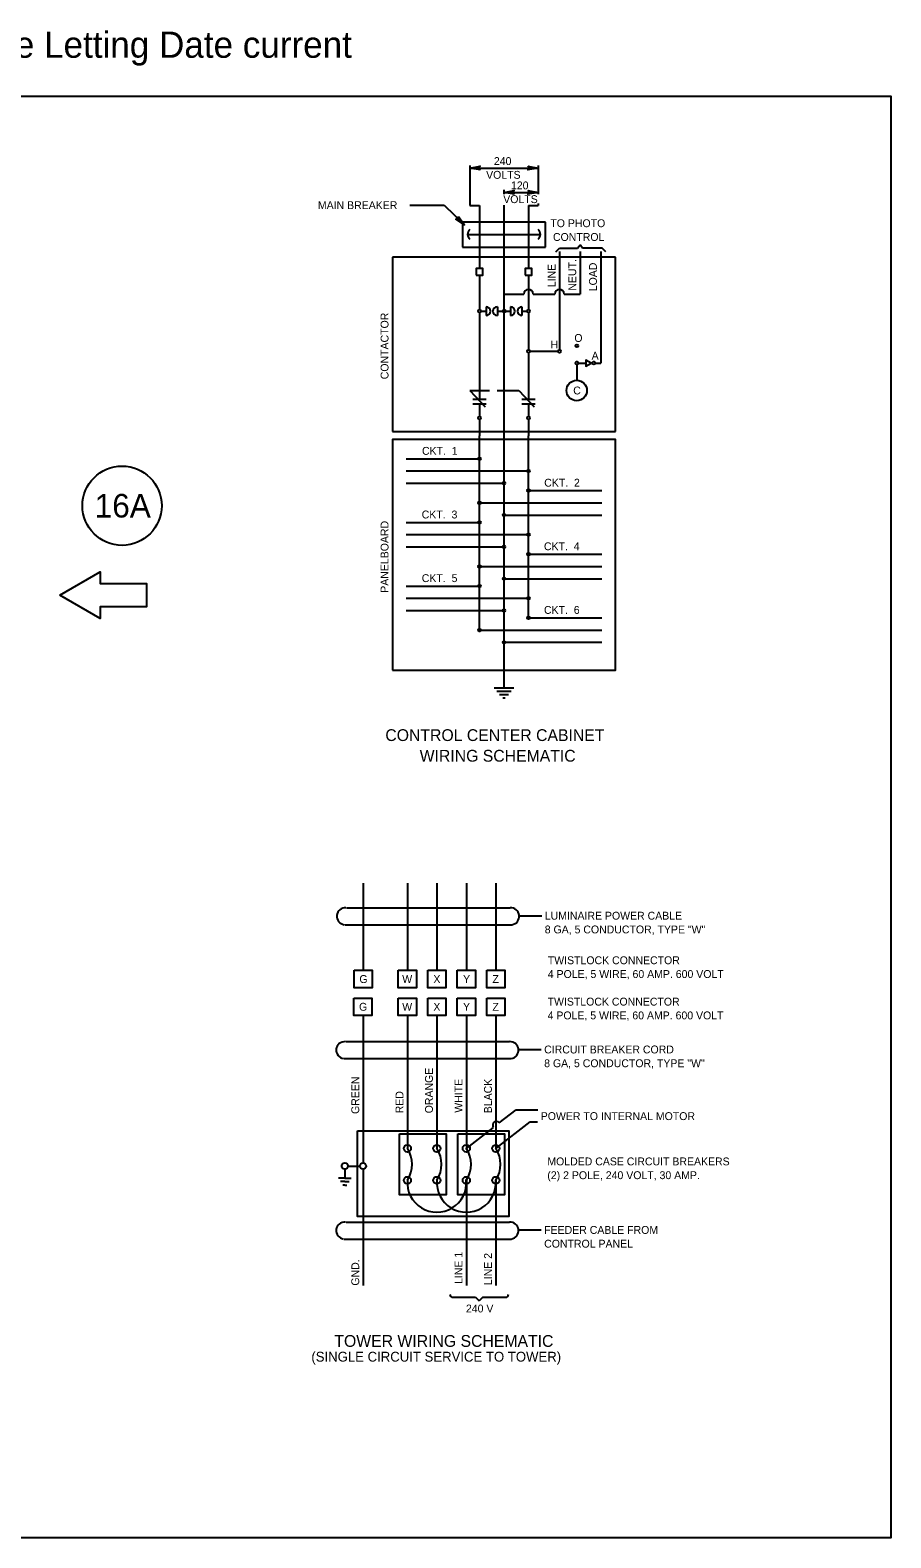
# Model space of a CAD drawing. Extents: x 99968 to 128667, y 90163 to 102182.
# Drawn here: x 117154 to 118467, y 93472 to 95772 of the extents above; entities that cross this region are included whole.
import ezdxf

# ---------------------------------------------------------------- set-up
doc = ezdxf.new("R2010")
doc.units = 0
for name, color, linetype in [('Border Prelim Stamp', 7, 'Continuous'), ('Default', 7, 'Continuous'), ('Level 7', 7, 'Continuous'), ('RD Standard Plans Active', 7, 'Continuous')]:
    doc.layers.add(name, color=color, linetype=linetype)

msp = doc.modelspace()

# ---------------------------------------------------------------- linework, layer by layer
at = {"layer": 'Border Prelim Stamp'}
msp.add_lwpolyline([(117198.9, 94910), (117260.4, 94945.5), (117260.4, 94927.7), (117331.3, 94927.7), (117331.3, 94892.3), (117260.4, 94892.3), (117260.4, 94874.5)], close=True, dxfattribs=at)
msp.add_ellipse((117294.1, 95046.6), major_axis=(-60.5, 0), ratio=0.999984, dxfattribs=at)
at = {"layer": 'Default'}
msp.add_lwpolyline([(115267.5, 95671.5), (118467.2, 95671.5), (118467.2, 93471.9), (115267.5, 93471.9)], close=True, dxfattribs=at)
at = {"layer": 'RD Standard Plans Active'}
for p, q in [((117824.6, 95565.5), (117824.6, 95504.5)), ((117824.6, 95561.8), (117929.1, 95561.8)), ((117929.1, 95565.5), (117929.1, 95521.7)), ((117876.9, 95522.1), (117876.9, 95528.3)), ((117876.9, 95524.7), (117929.1, 95524.7)), ((117929.1, 95507.7), (117929.1, 95504.5)), ((117733.4, 95505.1), (117785.6, 95505.1)), ((117785.6, 95505.1), (117816.8, 95475.1)), ((117824.6, 95504.5), (117839.5, 95504.5)), ((117839.5, 95504.5), (117839.5, 95432.1)), ((117876.9, 94768.5), (117876.9, 95505.3)), ((117914.2, 95504.5), (117929.1, 95504.5)), ((117914.2, 95504.5), (117914.2, 95432.1)), ((117940.4, 95479.1), (117813.3, 95479.1)), ((117813.3, 95479.1), (117813.3, 95441.1)), ((117821.3, 95460.6), (117932.4, 95460.6)), ((117940.4, 95441.1), (117940.4, 95479.1)), ((117813.3, 95441.1), (117940.4, 95441.1)), ((117956.1, 95433.8), (117961.8, 95439.5)), ((117961.8, 95439.5), (117988.8, 95439.5)), ((117988.8, 95439.5), (117992.9, 95444.6)), ((117996.9, 95439.5), (117992.9, 95444.6)), ((118026.7, 95439.5), (117996.9, 95439.5)), ((118032.4, 95433.8), (118026.7, 95439.5)), ((118046.8, 95425.9), (117706.6, 95425.9)), ((117706.6, 95425.9), (117706.6, 95159.7)), ((117839.5, 95432.1), (117839.5, 95408.7)), ((117914.2, 95432.1), (117914.2, 95408.7)), ((117961.5, 95434.4), (117961.5, 95284.4)), ((117993.1, 95434.4), (117993.1, 95369.5)), ((118024.6, 95434.4), (118024.6, 95264.3)), ((118046.8, 95159.7), (118046.8, 95425.9)), ((117839.5, 95398.1), (117839.5, 95345.7)), ((117914.2, 95398.2), (117914.2, 95345.7)), ((117876.8, 95369.5), (117907, 95369.5)), ((117921.4, 95369.5), (117954.3, 95369.5)), ((117968.7, 95369.5), (117993.1, 95369.5)), ((117849.6, 95350.1), (117849.6, 95336.8)), ((117866.8, 95350.1), (117866.8, 95336.8)), ((117887, 95350.1), (117887, 95336.8)), ((117904.1, 95350.1), (117904.1, 95336.8)), ((117839.5, 95341.3), (117839.5, 95209.2)), ((117841.7, 95343.5), (117849.6, 95343.5)), ((117866.8, 95343.5), (117874.6, 95343.5)), ((117879.1, 95343.5), (117887, 95343.5)), ((117904.1, 95343.5), (117912, 95343.5)), ((117914.2, 95341.3), (117914.2, 95284.4)), ((117914.2, 95280), (117914.2, 95209.2)), ((117916.4, 95282.2), (117959.3, 95282.2)), ((117987.8, 95262.1), (117987.8, 95238)), ((117990, 95264.3), (118001.9, 95264.3)), ((118016.3, 95264.3), (118024.6, 95264.3)), ((117824.6, 95222.6), (117848.2, 95197.4)), ((117824.6, 95222.6), (117854.9, 95222.6)), ((117829.2, 95209.2), (117849.8, 95209.2)), ((117866.6, 95222.6), (117899.3, 95222.6)), ((117899.3, 95222.6), (117922.9, 95197.4)), ((117903.9, 95209.2), (117924.5, 95209.2)), ((117829.2, 95201.8), (117849.8, 95201.8)), ((117839.5, 95201.8), (117839.5, 95182.7)), ((117903.9, 95201.8), (117924.5, 95201.8)), ((117914.2, 95201.8), (117914.2, 95182.7)), ((117839.5, 95178.3), (117839.5, 95153.1)), ((117914.2, 95178.3), (117914.2, 95153.1)), ((117706.6, 95159.7), (118046.8, 95159.7)), ((117839.5, 94856.9), (117839.5, 95153.1)), ((117914.2, 94875.6), (117914.2, 95153.1)), ((117727.5, 95118.3), (117839.5, 95118.3)), ((117727.5, 95099.6), (117914.2, 95099.6)), ((117727.5, 95080.9), (117876.9, 95080.9)), ((117914.2, 95069.7), (118026.2, 95069.7)), ((117839.5, 95051.1), (118026.2, 95051.1)), ((117876.9, 95032.4), (118026.2, 95032.4)), ((117727.5, 95021.2), (117839.5, 95021.2)), ((117727.5, 95002.5), (117914.2, 95002.5)), ((117727.5, 94983.9), (117876.9, 94983.9)), ((117839.5, 94954), (118026.2, 94954)), ((117914.2, 94972.7), (118026.2, 94972.7)), ((117876.9, 94935.3), (118026.2, 94935.3)), ((117727.5, 94924.1), (117839.5, 94924.1)), ((117727.5, 94905.4), (117914.2, 94905.4)), ((117727.5, 94886.8), (117876.9, 94886.8)), ((117914.2, 94875.6), (118026.2, 94875.6)), ((117839.5, 94856.9), (118026.2, 94856.9)), ((117876.9, 94838.2), (118026.2, 94838.2)), ((117861.9, 94768.5), (117891.8, 94768.5)), ((117865.9, 94763.5), (117887.8, 94763.5)), ((117869.9, 94758.6), (117883.8, 94758.6)), ((117874.9, 94753.6), (117878.8, 94753.6)), ((117661.9, 94470.7), (117661.9, 94337.8)), ((117729.4, 94470.7), (117729.4, 94337.8)), ((117774.4, 94470.7), (117774.4, 94337.8)), ((117819.4, 94470.7), (117819.4, 94337.8)), ((117864.4, 94470.7), (117864.4, 94337.8)), ((117636.7, 94433.2), (117886.1, 94433.2)), ((117633.9, 94407.3), (117889, 94407.3)), ((117900.1, 94421.1), (117934.6, 94421.1)), ((117661.9, 94268.7), (117661.9, 94043.9)), ((117729.4, 94268.7), (117729.4, 94066.1)), ((117774.4, 94268.7), (117774.4, 94066.1)), ((117819.4, 94268.7), (117819.4, 94066.1)), ((117864.4, 94268.7), (117864.4, 94066.1)), ((117635.8, 94229), (117885.2, 94229)), ((117632.9, 94203.1), (117888, 94203.1)), ((117899.1, 94217), (117933.7, 94217)), ((117864.4, 94066.1), (117916.7, 94106.5)), ((117869.6, 94105), (117895.5, 94125)), ((117895.5, 94125), (117928.5, 94125)), ((117916.7, 94106.5), (117928.2, 94106.5)), ((117819.4, 94066.1), (117860.8, 94098.2)), ((117634, 94034.2), (117634, 94020.7)), ((117638.7, 94039.2), (117656.9, 94039.2)), ((117634, 94020.7), (117624.2, 94020.7)), ((117634, 94015.6), (117627.3, 94015.6)), ((117634, 94020.7), (117643.8, 94020.7)), ((117634, 94015.6), (117640.6, 94015.6)), ((117661.9, 94033.6), (117661.9, 93857.1)), ((117819.4, 94017.4), (117819.4, 93857.1)), ((117864.4, 94017.4), (117864.4, 93857.1)), ((117633.9, 94010.2), (117631.1, 94010.2)), ((117634, 94010.2), (117636.8, 94010.2)), ((117635.8, 93953.7), (117885.2, 93953.7)), ((117899.1, 93941.7), (117933.7, 93941.7)), ((117632.9, 93927.8), (117888, 93927.8)), ((117798.6, 93839), (117833.3, 93839)), ((117833.3, 93839), (117839, 93833.3)), ((117844.6, 93839), (117839, 93833.3)), ((117844.6, 93839), (117879.4, 93839))]:
    msp.add_line(p, q, dxfattribs=at)
for points in [[(117840.3, 95559.2), (117824.6, 95561.8), (117840.3, 95564.5), (117837.8, 95561.8)], [(117913.4, 95564.5), (117929.1, 95561.8), (117913.4, 95559.2), (117915.9, 95561.8)], [(117892.5, 95522), (117876.9, 95524.7), (117892.5, 95527.4), (117890.1, 95524.7)], [(117913.4, 95527.4), (117929.1, 95524.7), (117913.4, 95522), (117915.9, 95524.7)], [(117807.3, 95487.9), (117816.8, 95475.1), (117803.6, 95484), (117807.3, 95484.2)], [(117834.3, 95398.2), (117844.8, 95398.2), (117844.8, 95408.7), (117834.3, 95408.7)], [(117909, 95398.2), (117919.5, 95398.2), (117919.5, 95408.7), (117909, 95408.7)], [(118009.8, 95264.3), (118001.9, 95268.8), (118001.9, 95259.7)], [(117706.6, 94795.5), (118046.8, 94795.5), (118046.8, 95147.5), (117706.6, 95147.5)], [(117648.1, 94337.8), (117675.7, 94337.8), (117675.7, 94311.1), (117648.1, 94311.1)], [(117715.6, 94337.8), (117743.2, 94337.8), (117743.2, 94311.1), (117715.6, 94311.1)], [(117760.6, 94337.8), (117788.2, 94337.8), (117788.2, 94311.1), (117760.6, 94311.1)], [(117805.6, 94337.8), (117833.2, 94337.8), (117833.2, 94311.1), (117805.6, 94311.1)], [(117850.6, 94337.8), (117878.2, 94337.8), (117878.2, 94311.1), (117850.6, 94311.1)], [(117647.6, 94295.4), (117675.2, 94295.4), (117675.2, 94268.7), (117647.6, 94268.7)], [(117715.6, 94295.4), (117743.2, 94295.4), (117743.2, 94268.7), (117715.6, 94268.7)], [(117760.6, 94295.4), (117788.2, 94295.4), (117788.2, 94268.7), (117760.6, 94268.7)], [(117805.6, 94295.4), (117833.2, 94295.4), (117833.2, 94268.7), (117805.6, 94268.7)], [(117850.6, 94295.4), (117878.2, 94295.4), (117878.2, 94268.7), (117850.6, 94268.7)], [(117653.4, 94093), (117884.4, 94093), (117884.4, 93962), (117653.4, 93962)], [(117717.4, 94088.2), (117788.6, 94088.2), (117788.6, 93995.3), (117717.4, 93995.3)], [(117806.6, 94088.2), (117877.8, 94088.2), (117877.8, 93995.3), (117806.6, 93995.3)]]:
    msp.add_lwpolyline(points, close=True, dxfattribs=at)
for centre, radius in [((117839.5, 95343.5), 2.21), ((117876.9, 95343.5), 2.21), ((117914.2, 95343.5), 2.21), ((117914.2, 95282.2), 2.21), ((117961.5, 95282.2), 2.21), ((117987.8, 95290.6), 2.21), ((117987.8, 95264.3), 2.21), ((118014.1, 95264.3), 2.21), ((117987.8, 95222.4), 15.6), ((117839.5, 95180.5), 2.21), ((117914.2, 95180.5), 2.21), ((117839.5, 95118.3), 1.99), ((117914.2, 95099.6), 1.99), ((117876.9, 95080.9), 1.99), ((117914.2, 95069.7), 1.99), ((117839.5, 95051.1), 1.99), ((117839.5, 95021.2), 1.99), ((117876.9, 95032.4), 1.99), ((117914.2, 95002.5), 1.99), ((117876.9, 94983.9), 1.99), ((117839.5, 94954), 1.99), ((117914.2, 94972.7), 1.99), ((117876.9, 94935.3), 1.99), ((117839.5, 94924.1), 1.99), ((117876.9, 94886.8), 1.99), ((117914.2, 94905.4), 1.99), ((117914.2, 94875.6), 1.99), ((117839.5, 94856.9), 1.99), ((117876.9, 94838.2), 1.99), ((117876.9, 94838.2), 1.99), ((117729.4, 94066.1), 5.54), ((117774.4, 94066.1), 5.54), ((117819.4, 94066.1), 5.54), ((117864.4, 94066.1), 5.54), ((117634, 94039.2), 4.73), ((117661.6, 94039.2), 4.73), ((117729.4, 94017.4), 5.54), ((117774.4, 94017.4), 5.54), ((117819.4, 94017.4), 5.54), ((117864.4, 94017.4), 5.54)]:
    msp.add_circle(centre, radius, dxfattribs=at)
for centre, radius, start, end in [((117830.3, 95460.6), 8.96, 126.8699, 233.1301), ((117923.5, 95460.6), 8.96, 306.8699, 53.1301), ((117914.2, 95369.5), 7.21, 0, 180), ((117961.5, 95369.5), 7.21, 0, 180), ((117849.6, 95343.5), 6.64, 270, 90), ((117866.7, 95343.5), 6.64, 90, 270), ((117887, 95343.5), 6.64, 270, 90), ((117904.1, 95343.5), 6.64, 90, 270), ((117634.8, 94420.2), 13, 85.7861, 261.6234), ((117887.1, 94420.2), 13, 278.3766, 94.2139), ((117633.9, 94216), 13, 85.7861, 261.6234), ((117886.1, 94216), 13, 278.3766, 94.2139), ((117865.2, 94101.6), 5.54, 38.1296, 217.1791), ((117691.8, 94041.7), 44.9, 327.1836, 33.0606), ((117736.7, 94041.8), 44.9, 327.0615, 32.9385), ((117781.7, 94041.8), 44.9, 327.0615, 32.9385), ((117826.7, 94041.8), 44.9, 327.0615, 32.9385), ((117774.4, 94013.7), 45, 175.318, 4.6724), ((117819.4, 94013.7), 45, 175.318, 4.6724), ((117633.9, 93940.7), 13, 85.7861, 261.6234), ((117886.1, 93940.7), 13, 278.3766, 94.2139), ((117798.7, 93843.4), 4.39, 181.1495, 270.7231), ((117879.4, 93843.4), 4.39, 269.2769, 358.8505)]:
    msp.add_arc(centre, radius, start, end, dxfattribs=at)

# ---------------------------------------------------------------- texts
at = {"layer": 'Border Prelim Stamp'}
msp.add_text('16A', height=36, dxfattribs=at).set_placement((117252.3, 95028.6))
at = {"layer": 'Level 7'}
msp.add_text('Effective Letting Date current', height=40, dxfattribs=at).set_placement((116955, 95730))
at = {"layer": 'RD Standard Plans Active'}
for s, height, p in [('240', 12, (117861.4, 95566.4)), ('VOLTS', 12, (117849.6, 95545.4)), ('120', 12, (117887.5, 95529.3)), ('MAIN BREAKER ', 12, (117592.9, 95499.1)), ('VOLTS', 12, (117875.7, 95508.3)), ('TO PHOTO', 12, (117947.6, 95471.6)), ('CONTROL', 12, (117951.6, 95450.6)), ('O', 12, (117984.2, 95296.5)), ('H', 12, (117948, 95286.5)), ('A', 12, (118010.6, 95269.5)), ('C', 12, (117982.5, 95216.4)), ('CKT.  1', 12, (117751.7, 95124.3)), ('CKT.  2', 12, (117938.2, 95075.7)), ('CKT.  3', 12, (117751.3, 95027.2)), ('CKT.  4', 12, (117937.8, 94978.7)), ('CKT.  5', 12, (117751.4, 94930.1)), ('CKT.  6', 12, (117937.9, 94881.6)), ('CONTROL CENTER CABINET', 18, (117695.8, 94687.6)), ('WIRING SCHEMATIC', 18, (117748.2, 94656.1)), (' LUMINAIRE POWER CABLE', 12, (117934.6, 94415.1)), (' 8 GA, 5 CONDUCTOR, TYPE "W"', 12, (117934.6, 94394.1)), ('TWISTLOCK CONNECTOR', 12, (117943.7, 94347.1)), ('4 POLE, 5 WIRE, 60 AMP. 600 VOLT', 12, (117943.7, 94326.1)), ('G', 12, (117656.2, 94318.4)), ('W', 12, (117721.6, 94318.4)), ('X', 12, (117769.1, 94318.4)), ('Y', 12, (117814.4, 94318.4)), ('Z', 12, (117859.2, 94318.4)), ('G', 12, (117655.7, 94276.1)), ('W', 12, (117721.6, 94276.1)), ('X', 12, (117769.1, 94276.1)), ('Y', 12, (117814.4, 94276.1)), ('Z', 12, (117859.2, 94276.1)), ('TWISTLOCK CONNECTOR', 12, (117943.4, 94284)), ('4 POLE, 5 WIRE, 60 AMP. 600 VOLT', 12, (117943.4, 94263)), (' CIRCUIT BREAKER CORD', 12, (117933.7, 94211)), (' 8 GA, 5 CONDUCTOR, TYPE "W"', 12, (117933.7, 94190)), (' POWER TO INTERNAL MOTOR', 12, (117928.5, 94109.3)), ('MOLDED CASE CIRCUIT BREAKERS', 12, (117943, 94040.2)), ('(2) 2 POLE, 240 VOLT, 30 AMP.', 12, (117943, 94019.2)), (' FEEDER CABLE FROM', 12, (117933.7, 93935.7)), (' CONTROL PANEL', 12, (117933.7, 93914.7)), ('240 V', 12, (117818.8, 93815.8)), ('TOWER WIRING SCHEMATIC', 18, (117618, 93763.3)), ('(SINGLE CIRCUIT SERVICE TO TOWER)', 15, (117582.9, 93740.8))]:
    msp.add_text(s, height=height, dxfattribs=at).set_placement(p)
for s, p in [('LINE', (117955.5, 95379.9)), ('NEUT.', (117987.1, 95374.7)), ('LOAD', (118018.6, 95373.8)), ('CONTACTOR', (117700.6, 95239.5)), ('PANELBOARD', (117700.6, 94913.8)), ('GREEN', (117655.9, 94118.6)), ('ORANGE', (117768.4, 94119.6)), ('BLACK', (117858.4, 94119.7)), ('RED', (117723.4, 94119.6)), ('WHITE', (117813.4, 94120.5)), ('LINE 1', (117813.4, 93859.2)), ('LINE 2', (117858.4, 93857.5)), ('GND.', (117655.9, 93856.7))]:
    msp.add_text(s, height=12, rotation=90, dxfattribs=at).set_placement(p)

doc.saveas('drawing.dxf')
